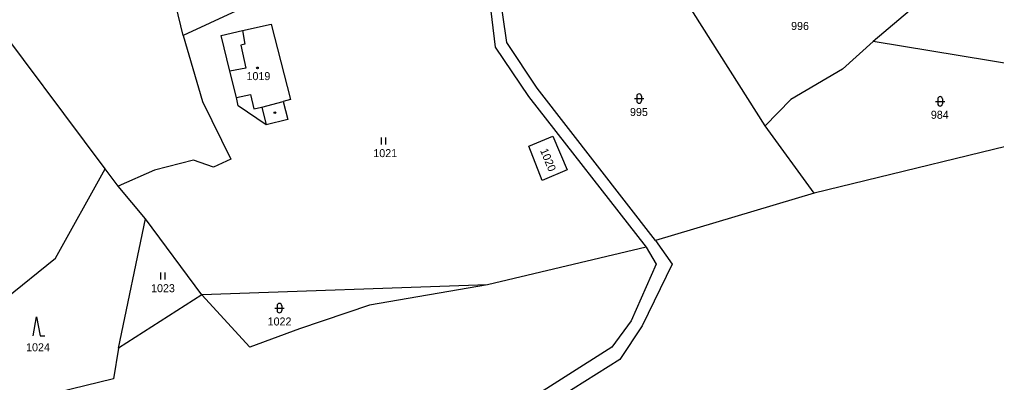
# Model space of a CAD drawing. Extents: x -670359 to -668019, y -978807 to -976674.
# Drawn here: x -669783.1 to -669575.5, y -977781.2 to -977704.1 of the extents above; entities that cross this region are included whole.
import ezdxf

# ---------------------------------------------------------------- set-up
doc = ezdxf.new("R2010")
doc.units = 0
for name, color, linetype in [('Hranice parcel', 7, 'Continuous'), ('Parcelní čísla', 7, 'Continuous'), ('Vnitřní kresba', 7, 'Continuous'), ('Značky budov', 7, 'Continuous'), ('Značky kultur', 7, 'Continuous')]:
    doc.layers.add(name, color=color, linetype=linetype)

msp = doc.modelspace()

# ---------------------------------------------------------------- linework, layer by layer
at = {"layer": 'Hranice parcel'}
for points in [[(-669683.61, -977696.35), (-669682.02, -977709.93)], [(-669679.55, -977708.95), (-669681.13, -977697.62)], [(-669588.52, -977697.54), (-669601.66, -977708.73)], [(-669764.89, -977735.76), (-669791.07, -977700.83)], [(-669730.38, -977699.11), (-669748.33, -977707.45)], [(-669624.67, -977726.69), (-669641.69, -977699.7)], [(-669748.33, -977707.45), (-669749.88, -977701.06)], [(-669740.23, -977707.44), (-669735.7, -977706.41)], [(-669735.7, -977706.41), (-669729.63, -977705.1)], [(-669729.63, -977705.1), (-669725.51, -977721.1)], [(-669748.33, -977707.45), (-669744.18, -977721.49)], [(-669738.37, -977715.06), (-669740.23, -977707.44)], [(-669673.1, -977718.67), (-669679.55, -977708.95)], [(-669601.66, -977708.73), (-669608.18, -977714.6)], [(-669564.68, -977714.82), (-669601.66, -977708.73)], [(-669682.02, -977709.93), (-669674.93, -977720.43)], [(-669736.98, -977720.65), (-669738.37, -977715.06)], [(-669608.18, -977714.6), (-669619.18, -977721.06)], [(-669647.97, -977751.04), (-669673.1, -977718.67)], [(-669744.18, -977721.49), (-669738.19, -977733.76)], [(-669736.65, -977722.4), (-669736.98, -977720.65)], [(-669725.51, -977721.1), (-669727.09, -977721.49)], [(-669727.09, -977721.49), (-669726.1, -977725.33)], [(-669674.93, -977720.43), (-669649.96, -977752.41)], [(-669619.18, -977721.06), (-669624.67, -977726.69)], [(-669730.65, -977726.47), (-669736.65, -977722.4)], [(-669726.1, -977725.33), (-669730.65, -977726.47)], [(-669614.2, -977740.93), (-669624.67, -977726.69)], [(-669674.87, -977730.98), (-669669.76, -977728.87)], [(-669669.76, -977728.87), (-669666.69, -977735.97)], [(-669562.44, -977728.39), (-669614.2, -977740.93)], [(-669672.03, -977738.24), (-669674.87, -977730.98)], [(-669746.11, -977733.97), (-669754.41, -977736.09)], [(-669741.86, -977735.46), (-669746.11, -977733.97)], [(-669738.19, -977733.76), (-669741.86, -977735.46)], [(-669775.42, -977754.76), (-669764.89, -977735.76)], [(-669762.15, -977739.49), (-669764.89, -977735.76)], [(-669754.41, -977736.09), (-669762.15, -977739.49)], [(-669666.69, -977735.97), (-669672.03, -977738.24)], [(-669756.28, -977746.41), (-669762.15, -977739.49)], [(-669614.2, -977740.93), (-669647.97, -977751.04)], [(-669762.05, -977773.86), (-669756.28, -977746.41)], [(-669744.31, -977762.55), (-669756.28, -977746.41)], [(-669649.96, -977752.41), (-669683.67, -977760.42)], [(-669649.96, -977752.41), (-669647.78, -977756.07)], [(-669647.97, -977751.04), (-669644.43, -977756.05)], [(-669786.17, -977763.37), (-669775.42, -977754.76)], [(-669647.78, -977756.07), (-669653.08, -977768.09)], [(-669644.43, -977756.05), (-669650.75, -977769.12)], [(-669683.67, -977760.42), (-669744.31, -977762.55)], [(-669683.67, -977760.42), (-669708.75, -977764.75)], [(-669744.31, -977762.55), (-669762.05, -977773.86)], [(-669734.16, -977773.67), (-669744.31, -977762.55)], [(-669708.75, -977764.75), (-669723.6, -977769.79)], [(-669653.08, -977768.09), (-669657.21, -977773.63)], [(-669650.75, -977769.12), (-669655.51, -977776.26)], [(-669723.6, -977769.79), (-669734.16, -977773.67)], [(-669762.05, -977773.86), (-669763.13, -977780.42)], [(-669657.21, -977773.63), (-669694.58, -977797.35)], [(-669655.51, -977776.26), (-669692.73, -977799.65)], [(-669763.13, -977780.42), (-669777.91, -977784.02)]]:
    msp.add_lwpolyline(points, dxfattribs=at)
at = {"layer": 'Vnitřní kresba'}
for points in [[(-669735.7, -977706.41), (-669735.2, -977709.29)], [(-669735.2, -977709.29), (-669736.08, -977709.53)], [(-669736.08, -977709.53), (-669735.02, -977714.4)], [(-669735.02, -977714.4), (-669738.37, -977715.06)], [(-669736.98, -977720.65), (-669734.03, -977719.99)], [(-669734.03, -977719.99), (-669733.26, -977723.08)], [(-669731.63, -977722.66), (-669727.09, -977721.49)], [(-669733.26, -977723.08), (-669731.63, -977722.66)], [(-669731.63, -977722.66), (-669730.65, -977726.47)]]:
    msp.add_lwpolyline(points, dxfattribs=at)
at = {"layer": 'Značky budov'}
msp.add_circle((-669732.53, -977714.35), 0.175, dxfattribs=at)
at = {"layer": 'Značky kultur'}
for p, q in [((-669652.43, -977720.87), (-669650.43, -977720.87)), ((-669651.93, -977720.37), (-669651.93, -977721.37)), ((-669650.93, -977720.37), (-669650.93, -977721.37)), ((-669588.47, -977721.46), (-669586.47, -977721.46)), ((-669587.97, -977720.96), (-669587.97, -977721.96)), ((-669586.97, -977720.96), (-669586.97, -977721.96)), ((-669706.22, -977729.11), (-669706.22, -977730.61)), ((-669705.22, -977730.61), (-669705.22, -977729.11)), ((-669753.13, -977757.79), (-669753.13, -977759.29)), ((-669752.13, -977759.29), (-669752.13, -977757.79)), ((-669728.36, -977764.86), (-669728.36, -977765.86)), ((-669727.36, -977764.86), (-669727.36, -977765.86)), ((-669728.86, -977765.36), (-669726.86, -977765.36))]:
    msp.add_line(p, q, dxfattribs=at)
msp.add_lwpolyline([(-669780.21, -977771.23), (-669779.46, -977767.23), (-669778.71, -977771.23), (-669777.71, -977771.23)], dxfattribs=at)
for centre in [(-669732.53, -977714.35), (-669728.82, -977723.85)]:
    msp.add_circle(centre, 0.175, dxfattribs=at)
for centre, start, end in [((-669651.43, -977720.37), 0, 180), ((-669651.43, -977721.37), 180, 0), ((-669587.47, -977720.96), 0, 180), ((-669587.47, -977721.96), 180, 0), ((-669727.86, -977764.86), 0, 180), ((-669727.86, -977765.86), 180, 0)]:
    msp.add_arc(centre, 0.5, start, end, dxfattribs=at)

# ---------------------------------------------------------------- texts
at = {"layer": 'Parcelní čísla'}
for s, p in [('996', (-669619.13, -977706.3)), ('1019', (-669734.85, -977716.95)), ('995', (-669653.36, -977724.57)), ('984', (-669589.43, -977725.16)), ('1021', (-669707.9, -977733.31)), ('1023', (-669755.13, -977761.99)), ('1022', (-669730.36, -977769.06)), ('1024', (-669781.69, -977774.54))]:
    msp.add_text(s, height=1.7, dxfattribs=at).set_placement(p)
msp.add_text('1020', height=1.7, rotation=292.2936, dxfattribs=at).set_placement((-669672.5, -977731.86))

doc.saveas('drawing.dxf')
